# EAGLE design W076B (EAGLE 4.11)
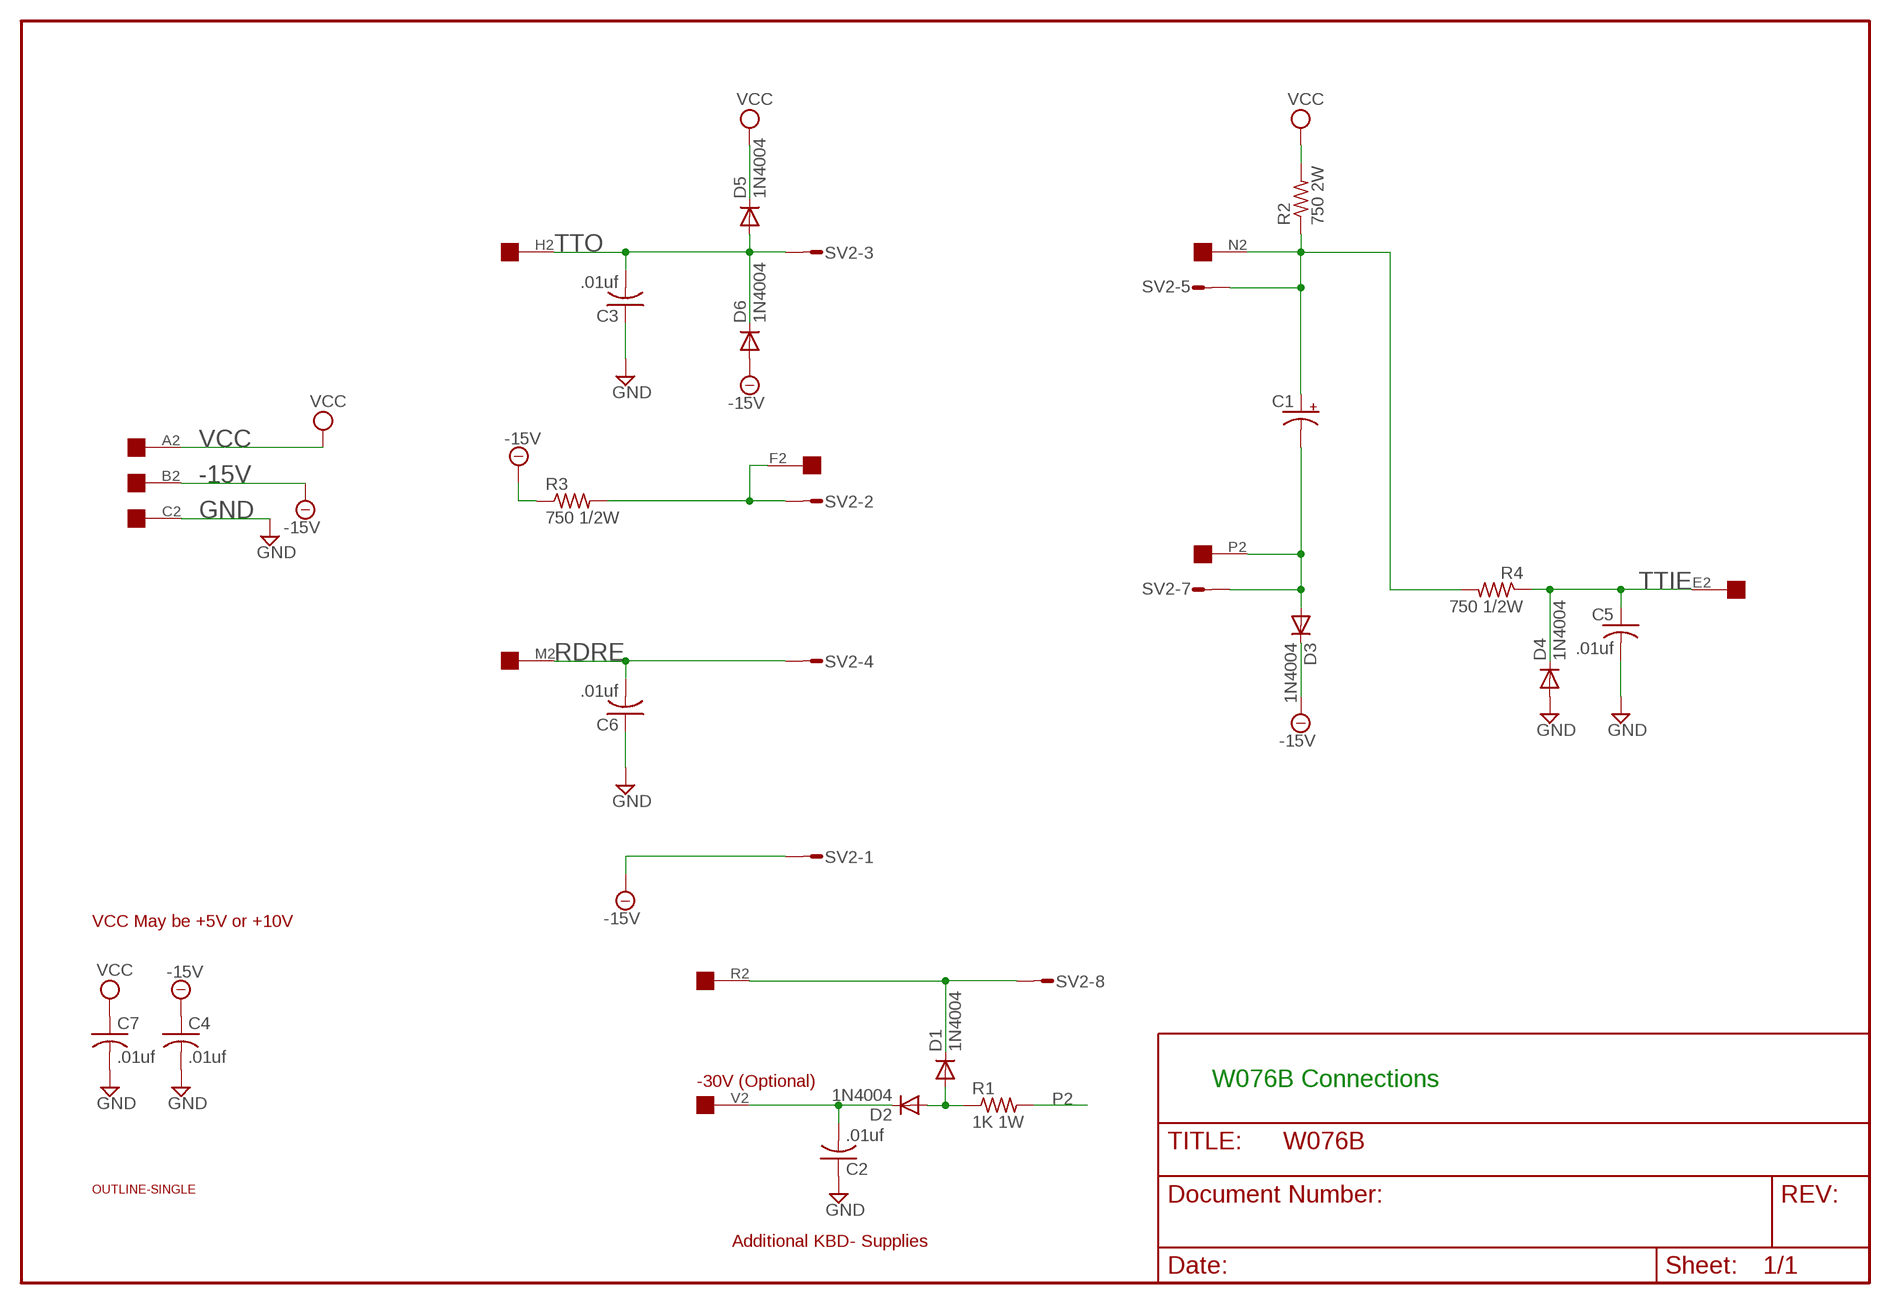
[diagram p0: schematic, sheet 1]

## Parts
C1  CPOL-USE22-6AXIAL  [E22-6]
C2  .01uf  C-US050-025X075  [C050-025X075]
C3  .01uf  C-US050-025X075  [C050-025X075]
C4  .01uf  C-US050-025X075  [C050-025X075]
C5  .01uf  C-US050-025X075  [C050-025X075]
C6  .01uf  C-US050-025X075  [C050-025X075]
C7  .01uf  C-US050-025X075  [C050-025X075]
D1  1N4004  1N4148  [DO35-10]
D2  1N4004  1N4148  [DO35-10]
D3  1N4004  1N4148  [DO35-10]
D4  1N4004  1N4148  [DO35-10]
D5  1N4004  1N4148  [DO35-10]
D6  1N4004  1N4148  [DO35-10]
EDGE  EDGE-1  [EDGE-CON1]
R1  1K 1W  R-US_0411/15  [0411/15]
R2  750 2W  R-US_0411/15  [0411/15]
R3  750 1/2W  R-US_0309/12  [0309/12]
R4  750 1/2W  R-US_0309/12  [0309/12]
SV2  L08P  [L08P]
U$1  OUTLINE-SINGLE  [SINGLE]

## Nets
-15V: C4.1 D3.C D6.A EDGE.B2 R3.1 SV2.1
GND: C2.1 C3.1 C4.2 C5.2 C6.1 C7.2 D4.A EDGE.C2
N$1: EDGE.F2 R3.2 SV2.2
N$3: D1.C EDGE.R2 SV2.8
N$5: C2.2 D2.C EDGE.V2
N$6: D1.A D2.A R1.1
N$7: C1.+ EDGE.N2 R2.1 R4.2 SV2.5
P2: C1.- D3.A EDGE.P2 R1.2 SV2.7
RDRE: C6.2 EDGE.M2 SV2.4
TTIE: C5.1 D4.C EDGE.E2 R4.1
TTO: C3.2 D5.A D6.C EDGE.H2 SV2.3
VCC: C7.1 D5.C EDGE.A2 R2.2
Unconnected: EDGE.D2 EDGE.J2 EDGE.K2 EDGE.L2 EDGE.S2 EDGE.T2 EDGE.U2 SV2.6

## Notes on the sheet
- VCC May be +5V or +10V
- -30V (Optional) | W076B Connections
- Additional KBD- Supplies

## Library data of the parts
C1 = rcl:CPOL-US: POLARIZED CAPACITOR, American symbol
C2-C7 = rcl:C-US: CAPACITOR, American symbol
D1-D6 = diode:1N4148: DIODE
EDGE = dec-con:EDGE-1: Single-Sided DEC Edge Connector -- (side 2)
R1-R4 = rcl:R-US_: RESISTOR, American symbol
SV2 = con-amp-mt:L08P: AMP MT CONNECTOR
U$1 = dec-con:OUTLINE-*: Board outlines for DEC boards.

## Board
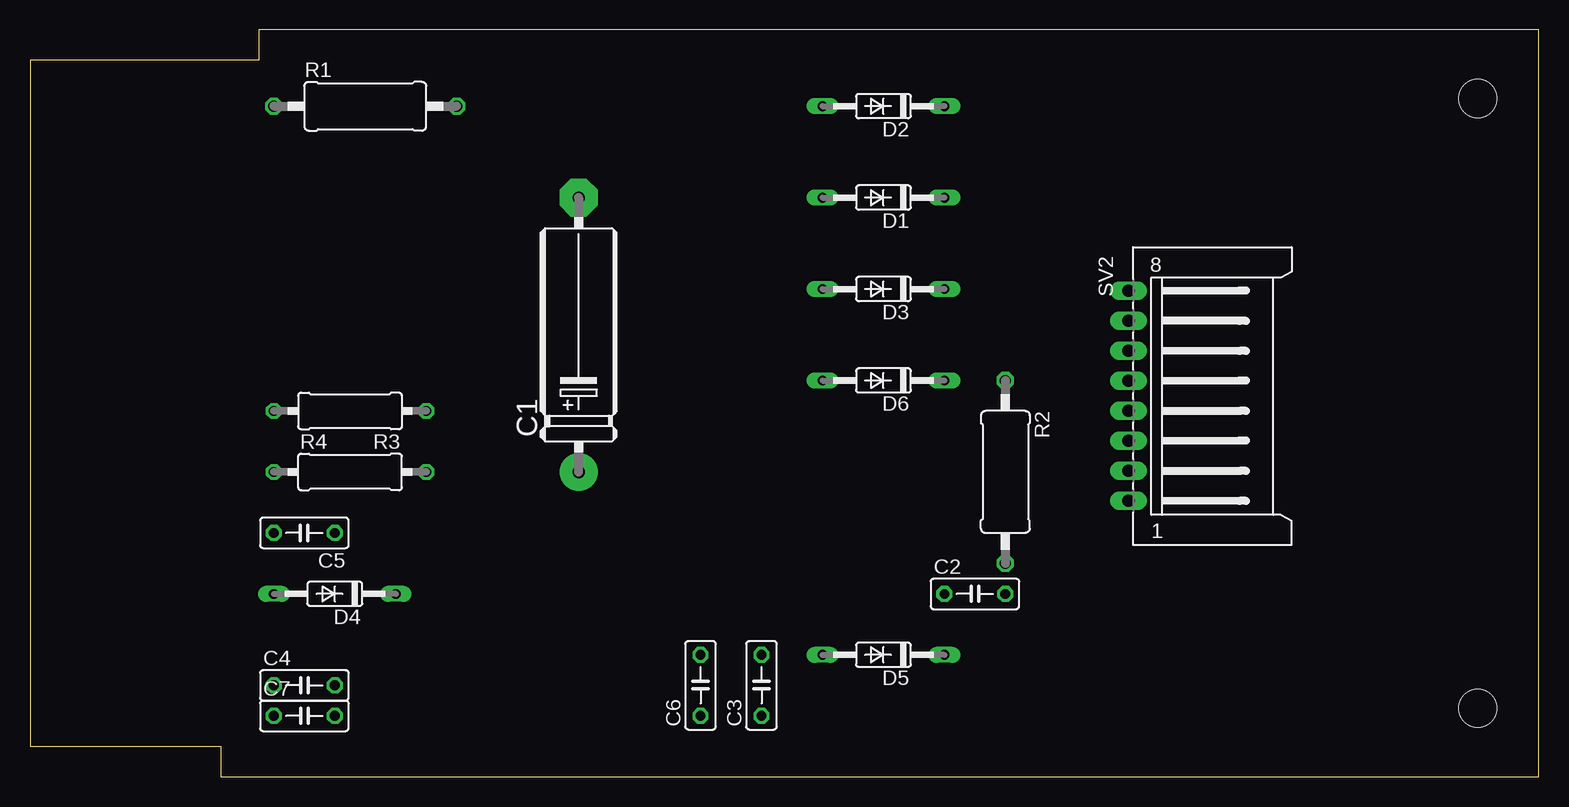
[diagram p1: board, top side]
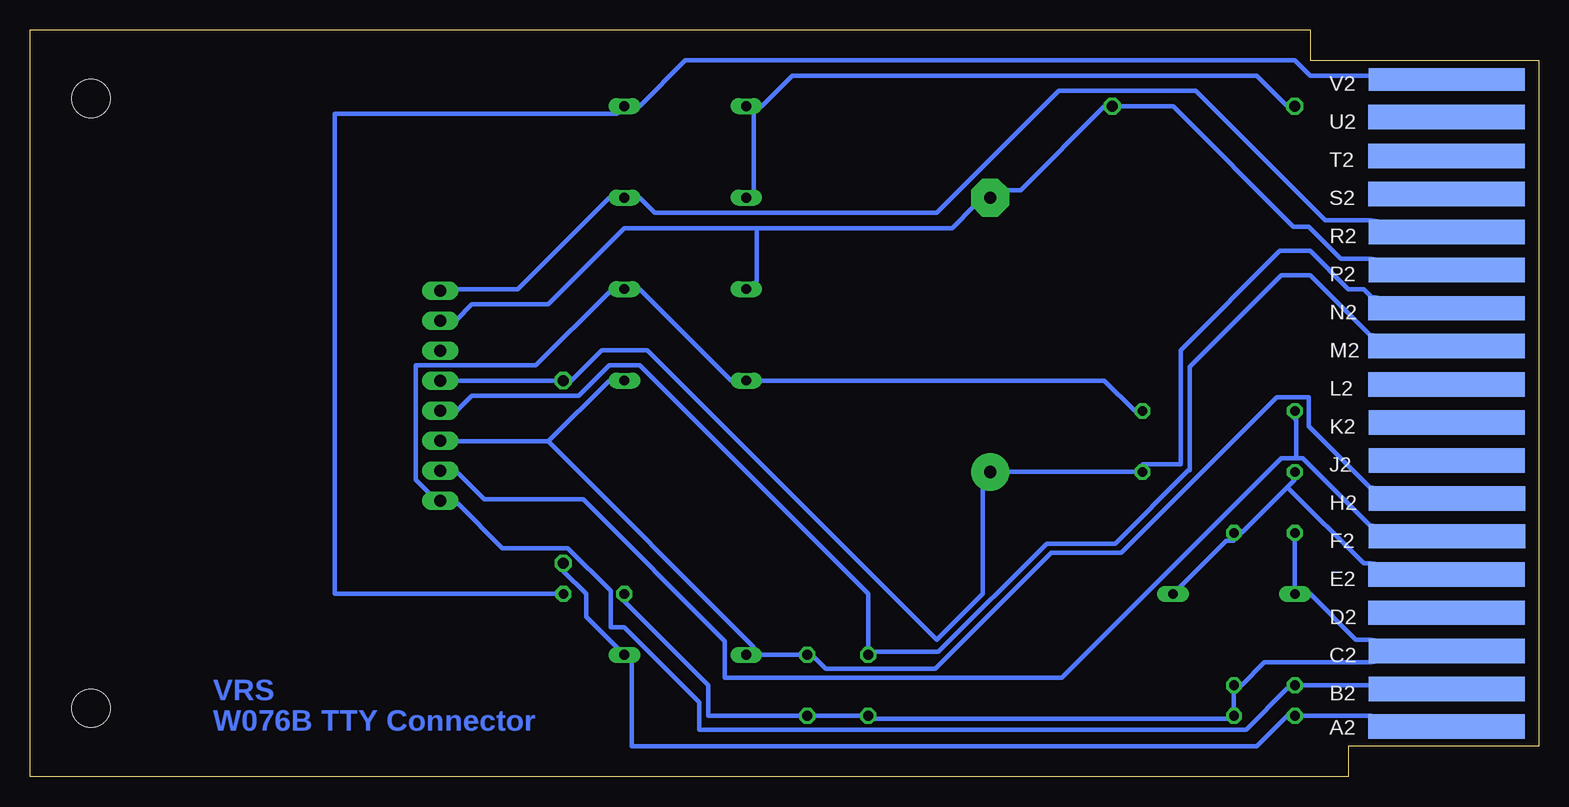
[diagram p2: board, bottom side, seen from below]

Size 125.73 x 62.23 mm. Coordinates in mm from the lower left corner, seen from the top.
Copper layers (1*16): Top 0.035mm / dielectric 1.5mm / Bottom 0.035mm
Design rules "15mils": minimum track width 15mil, minimum drill 24mil, track to track 15mil, track to pad 10mil, pad to pad 10mil, via to via 10mil, smd to smd 10mil, copper to edge 25mil, drill to drill 10mil, minimum pad ring 10mil, minimum via ring 8mil, stop-mask expansion 0mil, vias tented up to drill 0mil, thermal gap 10mil

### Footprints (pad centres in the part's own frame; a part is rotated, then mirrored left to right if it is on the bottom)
E22-6 = drill 1.016 pad 3.15 round: + -11.43,0 | drill 1.016 pad 3.15 octagon: - 11.43,0
C050-025X075 = drill 0.813 octagon: 1 -2.54,0; 2 2.54,0
DO35-10 = drill 0.813 long: A 5.08,0; C -5.08,0
EDGE-CON1 = smd 13.017 x 2.032 bottom: A2 7.69,4.194; B2 7.668,7.328; C2 7.668,10.49; D2 7.693,13.665; E2 7.693,16.84; F2 7.642,20.041; H2 7.642,23.19; J2 7.668,26.34; K2 7.668,29.515; L2 7.693,32.69; M2 7.693,35.89; N2 7.693,39.04; P2 7.668,42.24; R2 7.668,45.39; S2 7.693,48.565; T2 7.693,51.74; U2 7.693,54.966 | smd 13.017 x 1.905 bottom: V2 7.668,58.102
0411/15 = drill 0.914 octagon: 1 -7.62,0; 2 7.62,0
0309/12 = drill 0.813 octagon: 1 -6.35,0; 2 6.35,0
L08P = drill 1.016 long: 1 8.75,-6.25; 2 6.25,-6.25; 3 3.75,-6.25; 4 1.25,-6.25; 5 -1.25,-6.25; 6 -3.75,-6.25; 7 -6.25,-6.25; 8 -8.75,-6.25
SINGLE = hole 3.175: 120.65,56.515; 120.65,5.715

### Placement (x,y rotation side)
C1  45.72,36.83 90 top
C2  78.74,15.24 0 top
C3  60.96,7.62 90 top
C4  22.86,7.62 0 top
C5  22.86,20.32 180 top
C6  55.88,7.62 90 top
C7  22.86,5.08 0 top
D1  71.12,48.26 180 top
D2  71.12,55.88 180 top
D3  71.12,40.64 180 top
D4  25.4,15.24 180 top
D5  71.12,10.16 180 top
D6  71.12,33.02 180 top
EDGE  0,0 0 top
R1  27.94,55.88 0 top
R2  81.28,25.4 270 top
R3  26.67,30.48 180 top
R4  26.67,25.4 0 top
SV2  97.79,31.75 270 top
U$1  0,0 0 top

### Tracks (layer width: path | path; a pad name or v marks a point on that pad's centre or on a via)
-15V
  Bottom 0.381: R3.1 33.66,30.48 36.2,33.02 D6.A 67.31,33.02 74.93,40.64 D3.C 77.47,40.39 83.57,34.29 93.6,34.29 93.6,24.77 92.58,23.75 SV2.1 90.04,22.73 86.36,19.05 80.9,19.05 77.34,15.49 77.34,12.45 76.2,12.45 69.98,6.22 69.98,3.94 24.38,3.94 20.96,7.37 C4.1 13.97,7.62 EDGE.B2
GND
  Bottom 0.381: C5.2 D4.A 19.05,15.24 15.24,11.43 13.97,11.43 EDGE.C2 13.97,9.53 22.86,9.53 24.77,7.62 C4.2 C7.2 26.04,4.83 55.25,4.83 C6.1 C3.1 69.22,5.08 69.22,7.62 76.2,14.61 C2.1
N$1
  Bottom 0.381: R3.2 20.32,29.84 20.19,29.72 20.19,26.54 | 20.19,26.54 19.69,26.54 14.1,20.95 EDGE.F2 | SV2.2 90.04,25.27 87.88,23.11 79.63,23.11 67.82,11.3 67.82,8.26 39.75,8.26 21.46,26.54 20.19,26.54
N$3
  Bottom 0.381: SV2.8 90.17,40.64 85.09,40.64 77.47,48.26 D1.C 74.93,48.26 73.66,46.99 50.17,46.99 40.01,57.15 28.58,57.15 17.78,46.35 13.97,46.35 EDGE.R2
N$5
  Bottom 0.381: EDGE.V2 13.97,58.42 19.05,58.42 20.32,59.69 71.12,59.69 74.93,55.88 D2.C 76.84,55.24 100.33,55.24 100.33,15.24 C2.2
N$6
  Bottom 0.381: D1.A 65.41,48.9 65.41,55.24 D2.A 64.77,55.88 62.23,58.42 23.5,58.42 20.96,55.88 R1.1
N$7
  Bottom 0.381: EDGE.N2 13.97,40.01 14.61,40.64 15.88,40.64 19.05,43.81 21.59,43.81 29.85,35.56 29.85,26.04 33.02,26.04 R4.2 C1.+ 46.36,24.13 46.36,15.24 50.17,11.43 74.3,35.56 78.11,35.56 80.65,33.02 R2.1 90.17,33.02 SV2.5
P2
  Bottom 0.381: EDGE.P2 13.97,43.18 16.51,43.18 19.18,45.85 20.45,45.85 30.48,55.88 R1.2 36.2,55.88 43.18,48.9 44.45,48.9 C1.- 46.99,47.62 48.9,45.72 65.15,45.72 | 65.15,45.72 76.2,45.72 82.55,39.37 88.9,39.37 90.17,38.1 SV2.7 | D3.A 65.15,41.27 65.15,45.72
RDRE
  Bottom 0.381: SV2.4 90.17,30.48 88.9,31.75 80.01,31.75 77.47,34.29 74.93,34.29 55.88,15.24 C6.2 55.25,10.41 50.04,10.41 41.02,19.43 35.31,19.43 29.21,25.53 29.08,25.53 29.08,34.16 21.46,41.78 19.05,41.78 14.1,36.83 EDGE.M2
TTIE
  Bottom 0.381: D4.C 26.04,19.68 25.4,19.68 C5.1 24.77,20.32 20.96,24.13 | 20.96,24.13 20.32,24.77 R4.1 | 20.96,24.13 14.61,17.78 13.97,17.78 EDGE.E2
TTO
  Bottom 0.381: 82.55,27.94 77.47,33.02 D6.C | 82.55,27.94 90.17,27.94 SV2.3 | 82.55,27.94 65.41,10.79 D5.A C3.2 60.33,9.91 59.44,9.02 50.29,9.02 40.64,18.67 34.8,18.67 21.84,31.62 19.18,31.62 19.18,29.21 14.1,24.13 EDGE.H2
VCC
  Bottom 0.381: EDGE.A2 13.97,5.08 C7.1 20.96,5.08 23.5,2.54 75.57,2.54 75.57,9.53 D5.C 79.38,13.34 79.38,15.24 81.28,17.14 R2.2

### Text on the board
Bottom: VRS | W076B TTY Connector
